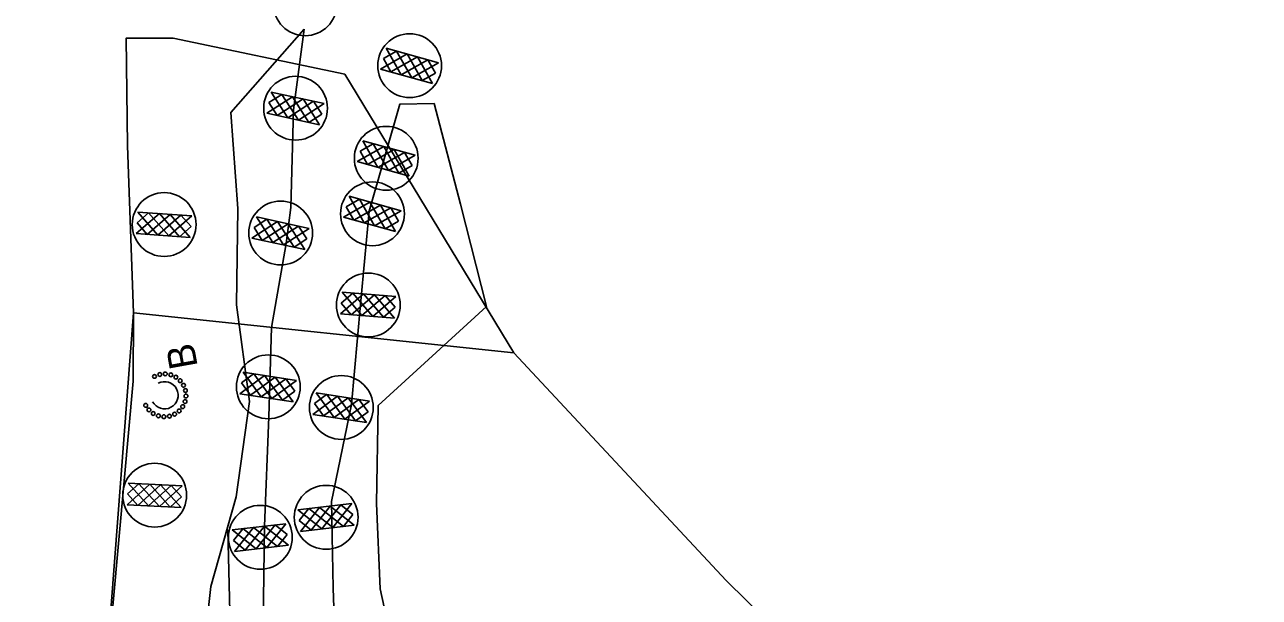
# Model space of a CAD drawing. Extents: x 400935 to 481562, y 415700 to 505362.
# Drawn here: x 474468 to 475127, y 504287 to 504592 of the extents above; entities that cross this region are included whole.
import ezdxf

# ---------------------------------------------------------------- set-up
doc = ezdxf.new("R2010")
doc.units = 0
for name, color, linetype in [('Excelsior Wattle Line Style Final', 7, 'Continuous'), ('Label B CG CELL', 7, 'Continuous'), ('Matting on Slope Note Final CELL', 7, 'Continuous'), ('Rock Pipe Inlet Sediment Trap Type B CG CELL', 7, 'Continuous'), ('Rock Silt Check Type A with Matting and PAM CG CELL', 7, 'Continuous'), ('Rock Silt Check Type A with Matting and PAM Final CELL', 7, 'Continuous'), ('Scratch_Level_4', 7, 'Continuous')]:
    doc.layers.add(name, color=color, linetype=linetype)

msp = doc.modelspace()

# ---------------------------------------------------------------- linework, layer by layer
at = {"layer": 'Excelsior Wattle Line Style Final'}
msp.add_line((474585.99, 503896.08), (474576.05, 504322.62), dxfattribs=at)
at = {"layer": 'Matting on Slope Note Final CELL'}
for p, q in [((474616.75, 504589.94), (474577.65, 504545.43)), ((474700.33, 504496.44), (474686.28, 504550.27)), ((474577.65, 504545.43), (474581.32, 504494.14)), ((474714.22, 504441.96), (474700.33, 504496.44)), ((474581.32, 504494.14), (474580.59, 504442.75)), ((474580.59, 504442.75), (474587.52, 504391.14)), ((474656.22, 504389), (474714.22, 504441.96)), ((474587.52, 504391.14), (474580.44, 504340.34)), ((474655.39, 504336.72), (474656.22, 504389)), ((474580.44, 504340.34), (474566.88, 504292.53)), ((474657.37, 504291.29), (474655.39, 504336.72)), ((474566.88, 504292.53), (474561.67, 504243.99)), ((474667.4, 504246.2), (474657.37, 504291.29))]:
    msp.add_line(p, q, dxfattribs=at)
for points in [[(474598.56, 503876.71), (474610.64, 503885.55), (474604.64, 503950.12), (474602.2, 504047.14), (474600.1, 504130.89), (474594.49, 504246.69), (474595.54, 504324.66), (474597.97, 504383.09), (474599.37, 504430.72), (474607.08, 504475.48), (474609.67, 504494.69), (474611.07, 504546.92), (474616.75, 504589.94)], [(474686.28, 504550.27), (474667.85, 504549.83), (474651.57, 504492.73), (474646.89, 504443.04), (474642.05, 504389.56), (474642.05, 504389.56), (474631.32, 504337.88), (474632.23, 504291.63), (474633.85, 504245.5), (474635.48, 504199.42), (474637.11, 504153.27), (474638.75, 504106.95), (474640.4, 504060.34), (474642.06, 504013.33), (474643.74, 503965.79), (474645.55, 503917.63), (474649.31, 503869.29), (474684.93, 503844.28)]]:
    msp.add_lwpolyline(points, dxfattribs=at)
at = {"layer": 'Rock Pipe Inlet Sediment Trap Type B CG CELL'}
for centre in [(474536.86, 504404.58), (474539.65, 504405.63), (474542.62, 504405.92), (474545.56, 504405.42), (474548.28, 504404.19), (474550.58, 504402.29), (474552.31, 504399.86), (474553.36, 504397.07), (474532.14, 504389.13), (474553.15, 504391.16), (474553.64, 504394.1), (474533.87, 504386.71), (474536.17, 504384.81), (474538.89, 504383.57), (474541.83, 504383.08), (474544.8, 504383.37), (474547.59, 504384.41), (474550.02, 504386.15), (474551.91, 504388.45)]:
    msp.add_circle(centre, 1.01, dxfattribs=at)
msp.add_arc((474542.22, 504394.5), 7.26, 208.01924, 118.01042, dxfattribs=at)
at = {"layer": 'Rock Silt Check Type A with Matting and PAM CG CELL'}
for p, q in [((474539.44, 504491.5), (474527.11, 504480.79)), ((474533.6, 504491.86), (474527.51, 504486.58)), ((474527.92, 504492.31), (474556.75, 504490.29)), ((474538.63, 504479.98), (474527.92, 504492.31)), ((474545.23, 504491.1), (474532.85, 504480.39)), ((474544.42, 504479.58), (474533.66, 504491.91)), ((474550.96, 504490.71), (474538.63, 504479.98)), ((474550.16, 504479.17), (474539.44, 504491.5)), ((474556.75, 504490.29), (474544.42, 504479.58)), ((474555.94, 504478.77), (474545.23, 504491.1)), ((474556.36, 504484.55), (474550.96, 504490.71)), ((474532.85, 504480.39), (474527.51, 504486.58)), ((474556.36, 504484.55), (474550.16, 504479.17)), ((474527.11, 504480.79), (474555.94, 504478.77)), ((474534.28, 504346.99), (474522.16, 504336.04)), ((474528.44, 504347.24), (474522.44, 504341.84)), ((474522.75, 504347.58), (474551.61, 504346.11)), ((474533.69, 504335.46), (474522.75, 504347.58)), ((474540.07, 504346.7), (474527.9, 504335.75)), ((474539.49, 504335.16), (474528.49, 504347.29)), ((474545.82, 504346.42), (474533.69, 504335.46)), ((474545.23, 504334.87), (474534.28, 504346.99)), ((474551.61, 504346.11), (474539.49, 504335.16)), ((474551.02, 504334.57), (474540.07, 504346.7)), ((474551.33, 504340.36), (474545.82, 504346.42)), ((474527.9, 504335.75), (474522.44, 504341.84)), ((474551.33, 504340.36), (474545.23, 504334.87)), ((474522.16, 504336.04), (474551.02, 504334.57))]:
    msp.add_line(p, q, dxfattribs=at)
for centre in [(474541.98, 504485.66), (474536.93, 504341.2)]:
    msp.add_circle(centre, 17.04, dxfattribs=at)
at = {"layer": 'Rock Silt Check Type A with Matting and PAM Final CELL'}
for p, q in [((474671.77, 504576.69), (474657.55, 504568.64)), ((474666.12, 504578.2), (474659.09, 504574.24)), ((474660.64, 504579.77), (474688.49, 504572.05)), ((474668.68, 504565.56), (474660.64, 504579.77)), ((474677.36, 504575.14), (474663.1, 504567.11)), ((474674.27, 504564.01), (474666.18, 504578.24)), ((474679.81, 504562.47), (474671.77, 504576.69)), ((474685.4, 504560.92), (474677.36, 504575.14)), ((474657.55, 504568.64), (474685.4, 504560.92)), ((474663.1, 504567.11), (474659.09, 504574.24)), ((474682.9, 504573.61), (474668.68, 504565.56)), ((474688.49, 504572.05), (474674.27, 504564.01)), ((474686.97, 504566.51), (474682.9, 504573.61)), ((474686.97, 504566.51), (474679.81, 504562.47)), ((474604.78, 504555.08), (474597.99, 504550.71)), ((474599.22, 504556.33), (474627.47, 504550.23)), ((474608.07, 504542.6), (474599.22, 504556.33)), ((474613.74, 504541.38), (474604.84, 504555.12)), ((474610.51, 504553.89), (474596.78, 504545.04)), ((474602.4, 504543.83), (474597.99, 504550.71)), ((474616.18, 504552.67), (474602.4, 504543.83)), ((474621.8, 504551.46), (474608.07, 504542.6)), ((474619.36, 504540.16), (474610.51, 504553.89)), ((474627.47, 504550.23), (474613.74, 504541.38)), ((474625.03, 504538.94), (474616.18, 504552.67)), ((474626.27, 504544.6), (474621.8, 504551.46)), ((474596.78, 504545.04), (474625.03, 504538.94)), ((474626.27, 504544.6), (474619.36, 504540.16)), ((474653.64, 504528.78), (474646.62, 504524.81)), ((474648.16, 504530.35), (474676.01, 504522.63)), ((474656.21, 504516.13), (474648.16, 504530.35)), ((474661.8, 504514.58), (474653.71, 504528.81)), ((474659.29, 504527.26), (474645.08, 504519.22)), ((474650.62, 504517.68), (474646.62, 504524.81)), ((474664.88, 504525.71), (474650.62, 504517.68)), ((474670.43, 504524.19), (474656.21, 504516.13)), ((474667.34, 504513.05), (474659.29, 504527.26)), ((474676.01, 504522.63), (474661.8, 504514.58)), ((474672.93, 504511.5), (474664.88, 504525.71)), ((474674.49, 504517.08), (474670.43, 504524.19)), ((474645.08, 504519.22), (474672.93, 504511.5)), ((474674.49, 504517.08), (474667.34, 504513.05)), ((474651.93, 504497.62), (474637.71, 504489.58)), ((474646.28, 504499.14), (474639.25, 504495.17)), ((474640.8, 504500.71), (474668.65, 504492.99)), ((474648.84, 504486.49), (474640.8, 504500.71)), ((474657.52, 504496.07), (474643.25, 504488.04)), ((474654.43, 504484.94), (474646.34, 504499.17)), ((474659.97, 504483.41), (474651.93, 504497.62)), ((474665.56, 504481.86), (474657.52, 504496.07)), ((474591.24, 504489.71), (474619.48, 504483.6)), ((474600.09, 504475.98), (474591.24, 504489.71)), ((474637.71, 504489.58), (474665.56, 504481.86)), ((474643.25, 504488.04), (474639.25, 504495.17)), ((474663.06, 504494.55), (474648.84, 504486.49)), ((474668.65, 504492.99), (474654.43, 504484.94)), ((474667.12, 504487.44), (474663.06, 504494.55)), ((474602.53, 504487.27), (474588.8, 504478.42)), ((474596.8, 504488.45), (474590.01, 504484.09)), ((474594.42, 504477.2), (474590.01, 504484.09)), ((474608.2, 504486.04), (474594.42, 504477.2)), ((474605.76, 504474.75), (474596.86, 504488.49)), ((474613.82, 504484.84), (474600.09, 504475.98)), ((474611.38, 504473.54), (474602.53, 504487.27)), ((474619.48, 504483.6), (474605.76, 504474.75)), ((474617.05, 504472.31), (474608.2, 504486.04)), ((474618.28, 504477.98), (474613.82, 504484.84)), ((474667.12, 504487.44), (474659.97, 504483.41)), ((474588.8, 504478.42), (474617.05, 504472.31)), ((474618.28, 504477.98), (474611.38, 504473.54)), ((474637.02, 504449.47), (474665.83, 504447.26)), ((474647.65, 504437.07), (474637.02, 504449.47)), ((474648.53, 504448.59), (474636.13, 504437.96)), ((474642.7, 504448.98), (474636.56, 504443.74)), ((474641.87, 504437.51), (474636.56, 504443.74)), ((474654.32, 504448.14), (474641.87, 504437.51)), ((474653.43, 504436.63), (474642.75, 504449.03)), ((474660.05, 504447.71), (474647.65, 504437.07)), ((474659.17, 504436.19), (474648.53, 504448.59)), ((474665.83, 504447.26), (474653.43, 504436.63)), ((474664.95, 504435.74), (474654.32, 504448.14)), ((474665.4, 504441.52), (474660.05, 504447.71)), ((474636.13, 504437.96), (474664.95, 504435.74)), ((474665.4, 504441.52), (474659.17, 504436.19)), ((474595.54, 504405.07), (474582.39, 504395.38)), ((474589.75, 504405.89), (474583.25, 504401.11)), ((474584.12, 504406.8), (474612.7, 504402.47)), ((474593.81, 504393.65), (474584.12, 504406.8)), ((474601.28, 504404.2), (474588.08, 504394.51)), ((474599.55, 504392.78), (474589.81, 504405.93)), ((474606.96, 504403.35), (474593.81, 504393.65)), ((474605.23, 504391.92), (474595.54, 504405.07)), ((474610.97, 504391.05), (474601.28, 504404.2)), ((474611.85, 504396.78), (474606.96, 504403.35)), ((474588.08, 504394.51), (474583.25, 504401.11)), ((474612.7, 504402.47), (474599.55, 504392.78)), ((474611.85, 504396.78), (474605.23, 504391.92)), ((474582.39, 504395.38), (474610.97, 504391.05)), ((474634.57, 504394.04), (474621.43, 504384.34)), ((474628.78, 504394.86), (474622.28, 504390.07)), ((474627.12, 504383.48), (474622.28, 504390.07)), ((474623.15, 504395.76), (474651.73, 504391.46)), ((474632.85, 504382.62), (474623.15, 504395.76)), ((474640.31, 504393.18), (474627.12, 504383.48)), ((474638.59, 504381.76), (474628.84, 504394.9)), ((474645.99, 504392.34), (474632.85, 504382.62)), ((474644.28, 504380.9), (474634.57, 504394.04)), ((474651.73, 504391.46), (474638.59, 504381.76)), ((474650.01, 504380.04), (474640.31, 504393.18)), ((474650.89, 504385.77), (474645.99, 504392.34)), ((474621.43, 504384.34), (474650.01, 504380.04)), ((474650.89, 504385.77), (474644.28, 504380.9)), ((474613.48, 504333.37), (474642.19, 504336.67)), ((474626.27, 504323.21), (474613.48, 504333.37)), ((474619.15, 504333.97), (474614.12, 504327.66)), ((474624.95, 504334.69), (474614.8, 504321.9)), ((474632.03, 504323.88), (474619.19, 504334.03)), ((474630.71, 504335.35), (474620.51, 504322.55)), ((474637.75, 504324.53), (474624.95, 504334.69)), ((474636.43, 504336.02), (474626.27, 504323.21)), ((474643.51, 504325.2), (474630.71, 504335.35)), ((474642.19, 504336.67), (474632.03, 504323.88)), ((474642.86, 504330.96), (474636.43, 504336.02)), ((474642.86, 504330.96), (474637.75, 504324.53)), ((474578.31, 504322.68), (474607.02, 504325.98)), ((474595.54, 504324.66), (474585.34, 504311.86)), ((474601.25, 504325.33), (474591.1, 504312.53)), ((474608.34, 504314.51), (474595.54, 504324.66)), ((474607.02, 504325.98), (474596.86, 504313.19)), ((474607.69, 504320.27), (474601.25, 504325.33)), ((474620.51, 504322.55), (474614.12, 504327.66)), ((474614.8, 504321.9), (474643.51, 504325.2)), ((474591.1, 504312.53), (474578.31, 504322.68)), ((474583.98, 504323.28), (474578.95, 504316.97)), ((474589.78, 504324), (474579.62, 504311.21)), ((474596.86, 504313.19), (474584.02, 504323.34)), ((474602.57, 504313.84), (474589.78, 504324)), ((474607.69, 504320.27), (474602.57, 504313.84)), ((474585.34, 504311.86), (474578.95, 504316.97)), ((474579.62, 504311.21), (474608.34, 504314.51))]:
    msp.add_line(p, q, dxfattribs=at)
for centre in [(474617.3, 504603.5), (474673.1, 504570.46), (474612.19, 504547.75), (474660.62, 504521.03), (474653.25, 504491.39), (474604.21, 504481.12), (474651.03, 504442.73), (474597.61, 504399.04), (474636.64, 504388.02), (474628.52, 504329.41), (474593.35, 504318.73)]:
    msp.add_circle(centre, 17.04, dxfattribs=at)
at = {"layer": 'Scratch_Level_4'}
msp.add_lwpolyline([(474622.89, 503758.26), (474610.09, 503858.5), (474582.45, 503900.64), (474562.43, 503946.88), (474467.5, 503793.86), (474481.43, 503959.46), (474508.73, 504217.08), (474525.69, 504438.48), (474522.41, 504527.71), (474521.7, 504585.06), (474546.76, 504585.2), (474546.76, 504585.2), (474546.76, 504585.2), (474546.76, 504585.2), (474546.76, 504585.2), (474638.46, 504565.86), (474728.78, 504417.22), (474842.23, 504295.6), (474941.08, 504198.57), (475006.21, 504066.62), (475061.71, 504006.75), (475126.97, 503907.83), (474615.72, 503889.9), (474621.71, 503834.05)], dxfattribs=at)
msp.add_lwpolyline([(474508.73, 504217.08), (474520.65, 504348.92), (474525.46, 504402.14), (474525.69, 504438.48), (474728.78, 504417.22), (474842.23, 504295.6), (474941.08, 504198.57)], close=True, dxfattribs=at)

# ---------------------------------------------------------------- texts
at = {"layer": 'Label B CG CELL'}
msp.add_text('B', height=15, rotation=100.25385, dxfattribs=at).set_placement((474559.98, 504409.92))

doc.saveas('drawing.dxf')
